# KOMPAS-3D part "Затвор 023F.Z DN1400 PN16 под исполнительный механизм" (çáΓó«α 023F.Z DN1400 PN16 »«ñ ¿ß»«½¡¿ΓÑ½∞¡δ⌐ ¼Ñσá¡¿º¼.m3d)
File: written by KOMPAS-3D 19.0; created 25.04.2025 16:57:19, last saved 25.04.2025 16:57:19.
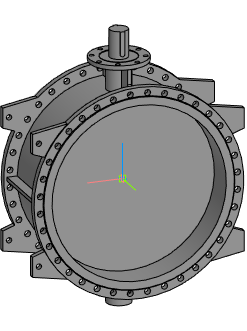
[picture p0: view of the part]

Document properties: Автор: Евгений; Полное имя файла: E:\Dendor Работа Сачек\3D для проекитирвщиков\1.7 Тип 023F.Z Затвор дисковый поворотный фланцевый с двумя эксцентриками\stp_Тип 023F.Z. Затвор под исполн. механизм\Затвор 023F.Z DN1400 PN16 под исполнительный механизм.m3d

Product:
- Part/product: Затвор 023F.Z DN1400 PN16 под исполнительный механизм

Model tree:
1. Операция без истории:1  (labels: Затвор 023F.Z DN1400 PN16 под исполнительный механизм)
